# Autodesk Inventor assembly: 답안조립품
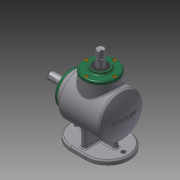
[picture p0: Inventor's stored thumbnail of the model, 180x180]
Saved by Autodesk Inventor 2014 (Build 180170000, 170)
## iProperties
Created: 2016-04
Part Number: 답안조립품
Document SubType Name: Assembly
Designer: USER
Author: USER
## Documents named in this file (14)
- C:\Users\USER\Desktop\460407V1005\답안조립품.iam
- C:\Users\USER\Desktop\460407V1005\본체.ipt
- C:\Users\USER\Desktop\460407V1005\M4.ipt
- C:\Users\USER\Desktop\460407V1005\메인 베벨기어.ipt
- C:\Users\USER\Desktop\460407V1005\메인 축.ipt
- 메인 축.ipt
- C:\Users\USER\Desktop\460407V1005\베어링 6203.ipt
- C:\Users\USER\Desktop\460407V1005\서브 베벨기어.ipt
- C:\Users\USER\Desktop\460407V1005\서브 축.ipt
- 서브 축.ipt
- C:\Users\USER\Desktop\460407V1005\오일실 17 32 8.ipt
- C:\Users\USER\Desktop\460407V1005\커버.ipt
- C:\Users\USER\Desktop\460407V1005\키 4x4.ipt
- C:\Users\USER\Desktop\460407V1005\키 5x5.ipt
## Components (8 placed, 1 different names)
1. M4:2
2. M4:3
3. M4:4
4. M4:5
5. M4:1
6. M4:6
7. M4:7
8. M4:8
